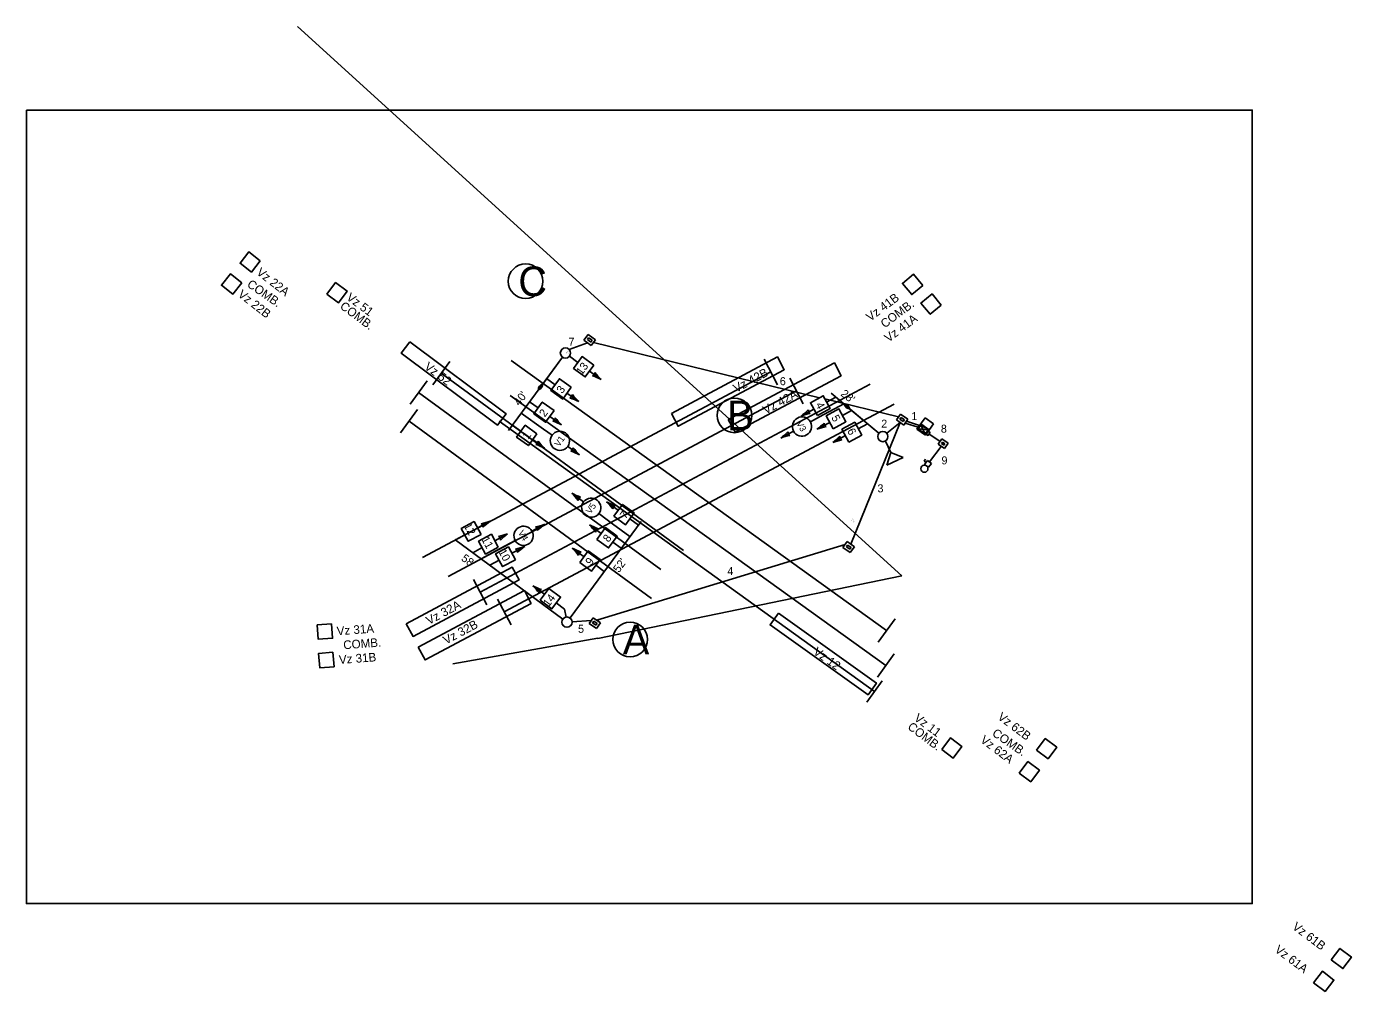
# Model space of a CAD drawing. Extents: x 973817 to 2958182, y 703625 to 1593455.
# Drawn here: x 977687 to 978239, y 704200 to 704601 of the extents above; entities that cross this region are included whole.
import ezdxf

# ---------------------------------------------------------------- set-up
doc = ezdxf.new("R2010")
doc.units = 0
for name, color, linetype in [('R_Fin Surface', 7, 'Continuous'), ('S_PAVEMENT_CROWN', 7, 'Continuous'), ('T_Conduit', 7, 'Continuous'), ('T_Detection Annot', 7, 'Continuous'), ('T_Detection Zones', 7, 'Continuous'), ('T_Drafting', 7, 'Continuous'), ('T_Indications', 7, 'Continuous'), ('T_Mast Arm', 7, 'Continuous'), ('T_PHASE SYMBOLS', 7, 'Continuous')]:
    doc.layers.add(name, color=color, linetype=linetype)

msp = doc.modelspace()

# ---------------------------------------------------------------- linework, layer by layer
at = {"layer": 'R_Fin Surface'}
for p, q in [((977856.23, 704452.09), (977863.31, 704461.77)), ((978045.08, 704349.89), (977888.82, 704462.22)), ((977994.09, 704462.73), (977999.73, 704452.14)), ((977846.83, 704444.09), (977853.92, 704453.78)), ((977996.91, 704457.43), (977852.01, 704380.26)), ((977859.77, 704456.93), (977960.59, 704383.21)), ((978004.77, 704454.82), (978010.41, 704444.23)), ((977850.37, 704448.94), (977951.19, 704375.21)), ((978007.59, 704449.52), (977862.69, 704372.35)), ((977875.95, 704365.88), (978038.26, 704452.33)), ((977885.98, 704357.63), (978048.28, 704444.08)), ((978044.74, 704335.35), (977888.49, 704447.68)), ((977842.85, 704432.14), (977849.93, 704441.83)), ((977846.39, 704436.98), (977947.21, 704363.26)), ((978040.05, 704324.55), (977883.8, 704436.89)), ((977878.8, 704360.53), (977873.16, 704371.13)), ((977888.83, 704352.28), (977883.19, 704362.87)), ((978041.57, 704345.01), (978048.58, 704354.76)), ((978041.24, 704330.47), (978048.25, 704340.22)), ((978036.84, 704320.09), (978043.27, 704329.02))]:
    msp.add_line(p, q, dxfattribs=at)
at = {"layer": 'S_PAVEMENT_CROWN'}
for p, q in [((978051.43, 704372.62), (977799.98, 704601.11)), ((978051.43, 704372.62), (977924.96, 704346.55)), ((977924.86, 704346.64), (977864.6, 704336.01))]:
    msp.add_line(p, q, dxfattribs=at)
msp.add_lwpolyline([(977687.19, 704566.32), (978197.19, 704566.32), (978197.19, 704236.32), (977687.19, 704236.32)], close=True, dxfattribs=at)
at = {"layer": 'T_Conduit'}
for p, q in [((977920.68, 704469.56), (977913, 704466.77)), ((978017.19, 704446.73), (977923.06, 704469.65)), ((978050.02, 704438.74), (978019.43, 704446.19)), ((978030.16, 704385.75), (978050.69, 704436.46)), ((978045.16, 704431.9), (978050.69, 704436.46)), ((978052.8, 704436.18), (978058.23, 704434.41)), ((978053.34, 704436.92), (978058.77, 704435.15)), ((978062.72, 704431.63), (978067.32, 704428.53)), ((978062.91, 704419.99), (978067.81, 704426.49)), ((978027.79, 704385.67), (977924.5, 704354.13)), ((977914.22, 704353.53), (977922.13, 704354.04))]:
    msp.add_line(p, q, dxfattribs=at)
at = {"layer": 'T_Detection Zones'}
for points in [[(977784.48, 704503.7), (977780.79, 704498.97), (977776.06, 704502.67), (977779.75, 704507.4)], [(977776.74, 704494.52), (977773.05, 704489.79), (977768.32, 704493.48), (977772.01, 704498.21)], [(978060.13, 704493.45), (978056.3, 704498.07), (978051.68, 704494.24), (978055.51, 704489.62)], [(977812.23, 704489.8), (977815.81, 704494.62), (977820.62, 704491.04), (977817.04, 704486.22)], [(978067.84, 704485.27), (978064.01, 704489.89), (978059.39, 704486.06), (978063.22, 704481.44)], [(977846.73, 704470.02), (977886.75, 704440.04), (977883.15, 704435.24), (977843.13, 704465.22)], [(977955.53, 704440.14), (977999.66, 704463.65), (978002.48, 704458.35), (977958.35, 704434.85)], [(977979.22, 704437.67), (978023.35, 704461.18), (978026.17, 704455.88), (977982.04, 704432.38)], [(977845.21, 704352.72), (977889.34, 704376.23), (977892.16, 704370.93), (977848.03, 704347.43)], [(977850.22, 704342.97), (977894.35, 704366.48), (977897.17, 704361.18), (977853.04, 704337.68)], [(978000.09, 704357.06), (978040.82, 704328.05), (978037.34, 704323.17), (977996.61, 704352.18)], [(977814.13, 704352.65), (977814.57, 704346.67), (977808.59, 704346.22), (977808.14, 704352.2)], [(977814.71, 704340.82), (977815.16, 704334.84), (977809.18, 704334.39), (977808.73, 704340.37)], [(978068.03, 704300.41), (978071.64, 704305.21), (978076.44, 704301.6), (978072.83, 704296.8)], [(978107.48, 704300.16), (978111.09, 704304.96), (978115.88, 704301.35), (978112.28, 704296.55)], [(978100.27, 704290.57), (978103.88, 704295.36), (978108.67, 704291.76), (978105.07, 704286.96)], [(978230.12, 704212.88), (978233.73, 704217.68), (978238.52, 704214.08), (978234.92, 704209.28)], [(978222.77, 704203.4), (978226.43, 704208.15), (978231.19, 704204.49), (978227.53, 704199.74)]]:
    msp.add_lwpolyline(points, close=True, dxfattribs=at)
at = {"layer": 'T_Drafting'}
for p, q in [((977919.16, 704470.65), (977920.86, 704473.02)), ((977919.16, 704470.65), (977922.2, 704468.46)), ((977920.56, 704470.88), (977921.09, 704471.63)), ((977920.56, 704470.88), (977921.98, 704469.86)), ((977920.86, 704473.02), (977923.91, 704470.83)), ((977921.09, 704471.63), (977922.51, 704470.6)), ((977921.98, 704469.86), (977922.51, 704470.6)), ((977922.2, 704468.46), (977923.91, 704470.83)), ((977910.18, 704463.59), (977887.74, 704433.09)), ((977910.18, 704463.59), (977901.84, 704452.25)), ((978040.35, 704433.2), (978022.08, 704448.56)), ((978041.88, 704431.92), (978029.57, 704442.26)), ((978049.17, 704437.55), (978050.88, 704439.92)), ((978049.17, 704437.55), (978052.22, 704435.36)), ((978050.57, 704437.78), (978051.1, 704438.53)), ((978050.57, 704437.78), (978051.99, 704436.76)), ((978050.88, 704439.92), (978053.92, 704437.73)), ((978051.1, 704438.53), (978052.52, 704437.5)), ((978051.99, 704436.76), (978052.52, 704437.5)), ((978052.22, 704435.36), (978053.92, 704437.73)), ((978061.06, 704438.33), (978057.71, 704433.67)), ((978064.57, 704435.8), (978061.06, 704438.33)), ((978061.22, 704431.14), (978057.71, 704433.67)), ((978059.38, 704435.44), (978058.17, 704433.75)), ((978061.14, 704431.6), (978058.17, 704433.75)), ((978058.17, 704433.75), (978062.36, 704433.29)), ((978062.82, 704433.37), (978059.31, 704435.9)), ((978062.36, 704433.29), (978059.38, 704435.44)), ((978061.13, 704431.62), (978059.38, 704435.44)), ((978062.36, 704433.29), (978061.14, 704431.6)), ((978064.57, 704435.8), (978061.22, 704431.14)), ((978044.57, 704428.69), (978046.89, 704423.87)), ((978066.52, 704427.42), (978068.11, 704429.63)), ((978066.52, 704427.42), (978069.11, 704425.56)), ((978067.91, 704427.65), (978068.34, 704428.24)), ((978067.91, 704427.65), (978068.88, 704426.95)), ((978068.11, 704429.63), (978070.7, 704427.77)), ((978068.34, 704428.24), (978069.3, 704427.55)), ((978068.88, 704426.95), (978069.3, 704427.55)), ((978069.11, 704425.56), (978070.7, 704427.77)), ((978045.24, 704418.64), (978046.89, 704423.87)), ((978052, 704421.89), (978045.24, 704418.64)), ((978046.89, 704423.87), (978052, 704421.89)), ((978061.31, 704421.19), (978060.71, 704420.39)), ((978062.11, 704420.59), (978060.9, 704418.99)), ((978063.7, 704419.38), (978062.11, 704420.59)), ((978061.5, 704419.79), (978060.71, 704420.39)), ((978062.5, 704417.79), (978060.9, 704418.99)), ((978063.7, 704419.38), (978062.5, 704417.79)), ((978026.93, 704384.48), (978028.64, 704386.85)), ((978026.93, 704384.48), (978029.98, 704382.29)), ((978028.33, 704384.71), (978028.87, 704385.45)), ((978028.33, 704384.71), (978029.75, 704383.69)), ((978028.64, 704386.85), (978031.68, 704384.66)), ((978028.87, 704385.45), (978030.29, 704384.43)), ((978029.75, 704383.69), (978030.29, 704384.43)), ((978029.98, 704382.29), (978031.68, 704384.66)), ((977921.27, 704352.85), (977922.98, 704355.22)), ((977922.98, 704355.22), (977926.02, 704353.03)), ((977921.27, 704352.85), (977924.32, 704350.66)), ((977922.67, 704353.08), (977923.2, 704353.83)), ((977922.67, 704353.08), (977924.09, 704352.06)), ((977923.2, 704353.83), (977924.62, 704352.8)), ((977924.09, 704352.06), (977924.62, 704352.8)), ((977924.32, 704350.66), (977926.02, 704353.03))]:
    msp.add_line(p, q, dxfattribs=at)
msp.add_lwpolyline([(978061.54, 704431.59), (978062.3, 704431.05), (978063.14, 704432.22), (978062.38, 704432.76)], dxfattribs=at)
for centre, radius in [((977911.45, 704465.31), 2.13), ((978043.51, 704430.55), 2.13), ((978060.8, 704417.19), 1.5), ((977912.09, 704353.4), 2.13)]:
    msp.add_circle(centre, radius, dxfattribs=at)
for centre, major_axis in [((977901.09, 704451.22), (-0.75, -1.02)), ((978028.6, 704443.07), (-0.971, 0.815))]:
    msp.add_ellipse(centre, major_axis=major_axis, ratio=0.40798, dxfattribs=at)
at = {"layer": 'T_Indications'}
for p, q in [((977916.59, 704461.37), (977913.08, 704463.94)), ((977907.15, 704452.14), (977903.62, 704454.67)), ((977921.48, 704457.8), (977926.36, 704454.23)), ((977912.07, 704448.6), (977916.98, 704445.08)), ((977900.04, 704442.47), (977896.51, 704445.01)), ((978017.17, 704438.72), (978027.25, 704444.2)), ((978020.14, 704444.89), (978023.96, 704446.96)), ((977902.36, 704433.61), (977893.02, 704440.27)), ((977904.96, 704438.94), (977909.86, 704435.41)), ((978014.82, 704441.99), (978009.51, 704439.1)), ((978017.17, 704438.72), (978013.37, 704436.65)), ((978026.72, 704439.36), (978030.53, 704441.43)), ((977892.92, 704432.8), (977889.39, 704435.34)), ((977902.36, 704433.61), (977905.88, 704431.1)), ((978006.34, 704432.82), (978001.01, 704429.93)), ((978021.39, 704436.46), (978016.09, 704433.57)), ((978033.29, 704433.83), (978037.11, 704435.9)), ((977897.84, 704429.27), (977902.74, 704425.74)), ((977912.39, 704426.45), (977917.33, 704422.93)), ((978027.97, 704430.93), (978022.67, 704428.04)), ((977918.97, 704403.35), (977914.12, 704406.98)), ((977928.84, 704395.96), (977925.38, 704398.56)), ((977933.4, 704399.9), (977928.52, 704403.47)), ((977874.87, 704392.54), (977880.18, 704395.42)), ((977897.53, 704391.18), (977902.85, 704394.07)), ((977926.29, 704390.24), (977921.41, 704393.8)), ((977938.29, 704396.33), (977941.8, 704393.76)), ((977869.55, 704389.64), (977865.71, 704387.55)), ((977882.06, 704387.24), (977887.37, 704390.13)), ((977886.7, 704385.29), (977890.5, 704387.35)), ((977876.74, 704384.35), (977872.9, 704382.26)), ((977889.18, 704382.01), (977894.48, 704384.89)), ((977919.17, 704380.57), (977914.3, 704384.14)), ((977931.18, 704386.66), (977934.69, 704384.1)), ((977883.85, 704379.11), (977880.01, 704377.02)), ((977924.07, 704377), (977927.57, 704374.43)), ((977902.72, 704364.94), (977897.85, 704368.51)), ((977907.62, 704361.37), (977911.12, 704358.8)), ((977911.09, 704358.82), (977911.7, 704355.49))]:
    msp.add_line(p, q, dxfattribs=at)
for points in [[(977923.27, 704460.24), (977919.69, 704455.35), (977914.8, 704458.93), (977918.38, 704463.82)], [(977913.84, 704451.06), (977910.3, 704446.14), (977905.38, 704449.68), (977908.92, 704454.6)], [(977906.73, 704441.39), (977903.19, 704436.48), (977898.27, 704440.01), (977901.81, 704444.93)], [(978016.26, 704439.33), (978013.37, 704444.65), (978018.69, 704447.55), (978021.58, 704442.22)], [(978022.84, 704433.8), (978019.95, 704439.12), (978025.27, 704442.02), (978028.16, 704436.69)], [(977899.61, 704431.72), (977896.07, 704426.81), (977891.15, 704430.34), (977894.69, 704435.26)], [(978029.42, 704428.27), (978026.52, 704433.59), (978031.85, 704436.49), (978034.74, 704431.16)], [(977931.6, 704397.46), (977935.19, 704402.35), (977940.08, 704398.77), (977936.5, 704393.88)], [(977876.32, 704389.88), (977873.42, 704395.2), (977868.1, 704392.3), (977871, 704386.98)], [(977883.51, 704384.58), (977880.61, 704389.9), (977875.29, 704387.01), (977878.19, 704381.69)], [(977924.5, 704387.79), (977928.08, 704392.68), (977932.97, 704389.1), (977929.39, 704384.22)], [(977890.63, 704379.35), (977887.73, 704384.67), (977882.4, 704381.77), (977885.3, 704376.45)], [(977917.38, 704378.13), (977920.96, 704383.02), (977925.86, 704379.44), (977922.28, 704374.55)], [(977900.93, 704362.5), (977904.51, 704367.39), (977909.41, 704363.81), (977905.83, 704358.92)]]:
    msp.add_lwpolyline(points, close=True, dxfattribs=at)
for points in [[(977928.84, 704395.96), (977931.04, 704394.32), (977938.24, 704388.93)], [(977886.7, 704385.29), (977884.29, 704383.98), (977876.38, 704379.68)]]:
    msp.add_lwpolyline(points, dxfattribs=at)
for centre, major_axis, ratio, start_param, end_param in [((977922.11, 704457.34), (1.63, -0.07), 0.998816, 5.137096, 6.248777), ((977912.71, 704428.14), (-29.45, 1.22), 0.998816, 4.272384, 4.407439), ((977947.12, 704475.12), (29.45, -1.22), 0.998816, 3.836841, 3.971897), ((977912.7, 704448.15), (1.63, -0.05), 0.998816, 5.137096, 6.248777), ((977937.57, 704466.13), (29.46, -0.99), 0.998816, 3.836841, 3.971897), ((977903.54, 704418.88), (-29.46, 0.99), 0.998816, 4.272384, 4.407439), ((977905.59, 704438.48), (1.63, -0.05), 0.998816, 5.137096, 6.248777), ((977896.42, 704409.21), (-29.46, 0.99), 0.998816, 4.272384, 4.407439), ((977930.46, 704456.46), (29.46, -0.99), 0.998816, 3.836841, 3.971897), ((977991.75, 704462.58), (13.68, 26.1), 0.998816, 4.272384, 4.407439), ((978019.53, 704411.4), (-13.68, -26.1), 0.998816, 3.836841, 3.971897), ((978014.14, 704441.62), (-0.76, -1.44), 0.998816, 5.137096, 6.248777), ((977983.22, 704453.4), (25.89, 14.08), 0.999186, 4.862665, 4.997721), ((978005.64, 704432.44), (-1.43, -0.78), 0.999186, 5.727378, 6.839059), ((977998.33, 704457.05), (13.68, 26.1), 0.998816, 4.272384, 4.407439), ((978026.11, 704405.88), (-13.68, -26.1), 0.998816, 3.836841, 3.971897), ((978020.71, 704436.09), (-0.76, -1.44), 0.998816, 5.137096, 6.248777), ((977898.47, 704428.81), (1.63, -0.05), 0.998816, 5.137096, 6.248777), ((977889.31, 704399.54), (-29.46, 0.99), 0.998816, 4.272384, 4.407439), ((977923.34, 704446.79), (29.46, -0.99), 0.998816, 3.836841, 3.971897), ((978011.05, 704402.24), (-25.89, -14.08), 0.999186, 4.427123, 4.562178), ((978004.9, 704451.52), (13.68, 26.1), 0.998816, 4.272384, 4.407439), ((978032.68, 704400.35), (-13.68, -26.1), 0.998816, 3.836841, 3.971897), ((978027.29, 704430.56), (-0.76, -1.44), 0.998816, 5.137096, 6.248777), ((977913.04, 704425.99), (1.33, -0.95), 0.999186, 5.727378, 6.839059), ((977904.01, 704396.66), (-23.99, 17.12), 0.999186, 4.862665, 4.997721), ((977937.83, 704444.07), (23.99, -17.12), 0.999186, 4.427123, 4.562178), ((977893.13, 704386.3), (25.74, 14.35), 0.999533, 0.134406, 0.269462), ((977928.05, 704432.95), (-25.74, -14.35), 0.999533, 0.569949, 0.705004), ((977918.34, 704403.83), (-1.42, -0.79), 0.999533, 4.576253, 5.687935), ((977907.75, 704382.58), (-29.45, 1.09), 0.998761, 3.832296, 3.967352), ((977942.17, 704429.56), (29.45, -1.09), 0.998761, 4.267839, 4.402894), ((977932.77, 704400.36), (-1.63, 0.06), 0.998761, 5.132551, 6.244232), ((977870.11, 704423.09), (29.34, -2.83), 0.998761, 5.021884, 5.156939), ((977875.55, 704392.9), (1.62, -0.16), 0.998761, 0.038953, 1.150634), ((977897.99, 704371.96), (-29.34, 2.83), 0.998761, 5.457426, 5.592482), ((977892.8, 704421.77), (23.41, -17.9), 0.999533, 5.578181, 5.713237), ((977898.23, 704391.56), (-1.29, 0.99), 0.999533, 3.736843, 4.848524), ((977920.66, 704370.59), (-23.41, 17.9), 0.999533, 6.013724, 6.148779), ((977900.64, 704372.92), (-29.45, 1.09), 0.998761, 3.832296, 3.967352), ((977935.06, 704419.89), (29.45, -1.09), 0.998761, 4.267839, 4.402894), ((977877.3, 704417.8), (29.34, -2.83), 0.998761, 5.021884, 5.156939), ((977882.74, 704387.61), (1.62, -0.16), 0.998761, 0.038953, 1.150634), ((977905.18, 704366.67), (-29.34, 2.83), 0.998761, 5.457426, 5.592482), ((977925.66, 704390.69), (-1.63, 0.06), 0.998761, 5.132551, 6.244232), ((977884.42, 704412.56), (29.34, -2.83), 0.998761, 5.021884, 5.156939), ((977889.86, 704382.37), (1.62, -0.16), 0.998761, 0.038953, 1.150634), ((977912.29, 704361.43), (-29.34, 2.83), 0.998761, 5.457426, 5.592482), ((977893.53, 704363.25), (-29.45, 1.09), 0.998761, 3.832296, 3.967352), ((977927.95, 704410.22), (29.45, -1.09), 0.998761, 4.267839, 4.402894), ((977918.55, 704381.03), (-1.63, 0.06), 0.998761, 5.132551, 6.244232), ((977877.08, 704347.62), (-29.45, 1.09), 0.998761, 3.832296, 3.967352), ((977911.5, 704394.59), (29.45, -1.09), 0.998761, 4.267839, 4.402894), ((977902.1, 704365.4), (-1.63, 0.06), 0.998761, 5.132551, 6.244232)]:
    msp.add_ellipse(centre, major_axis=major_axis, ratio=ratio, start_param=start_param, end_param=end_param, dxfattribs=at)
for centre, major_axis, ratio in [((978009.85, 704434.74), (-3.51, -1.91), 0.999186), ((977909.14, 704428.78), (3.26, -2.32), 0.999186), ((977922.18, 704400.95), (3.49, 1.95), 0.999533), ((977894.02, 704389.26), (-3.18, 2.43), 0.999533)]:
    msp.add_ellipse(centre, major_axis=major_axis, ratio=ratio, dxfattribs=at)
at = {"layer": 'T_Mast Arm'}
for p, q in [((977913.35, 704355.11), (977942.92, 704395.27)), ((977910.37, 704354.66), (977865.38, 704387.78))]:
    msp.add_line(p, q, dxfattribs=at)
at = {"layer": 'T_PHASE SYMBOLS'}
for centre in [(977894.87, 704495.14), (977981.74, 704439.38), (977938.35, 704346.15)]:
    msp.add_circle(centre, 7.21, dxfattribs=at)

# ---------------------------------------------------------------- texts
for s, rotation, p in [('N=704465.31  ', 53.247, (977911.56, 704465.22)), ('E=977911.45  ', 53.247, (977911.75, 704465.08)), ('Sta=18+31.96 ', 53.247, (977911.94, 704464.94)), ("Off=38.74' ", 53.247, (977912.14, 704464.79)), ('11.81m ', 53.247, (977912.33, 704464.65)), ('N=704395.48  ', 53.9355, (978030.48, 704395.4)), ('E=978030.37  ', 53.9355, (978030.68, 704395.26)), ('Sta=16+94.25 ', 53.9355, (978030.87, 704395.12)), ("Off=53.13' ", 53.9355, (978031.07, 704394.97)), ('16.19m ', 53.9355, (978031.26, 704394.83)), ('N=704354.13  ', 53.6305, (977924.61, 704354.04)), ('E=977924.50  ', 53.6305, (977924.8, 704353.9)), ('Sta=17+55.26 ', 53.6305, (977925, 704353.76)), ("Off=42.79' ", 53.6305, (977925.19, 704353.62)), ('13.04m ', 53.6305, (977925.38, 704353.47))]:
    msp.add_text(s, height=0.14, rotation=rotation).set_placement(p)
at = {"layer": 'S_PAVEMENT_CROWN'}
for s, p in [('7', (977912.72, 704468.36)), ('6', (978000.65, 704451.91)), ('2', (978042.84, 704434.26)), ('1', (978055.38, 704437.38)), ('8', (978067.67, 704432.16)), ('9', (978067.92, 704418.98)), ('3', (978041.29, 704407.35)), ('4', (977978.8, 704372.96)), ('5', (977916.7, 704348.93))]:
    msp.add_text(s, height=3.33, dxfattribs=at).set_placement(p)
at = {"layer": 'T_Detection Annot'}
for s, rotation, p in [('Vz 22A', 322.0317, (977782.59, 704498.27)), ('COMB.', 325.1942, (977778.67, 704493.17)), ('Vz 22B', 322.0317, (977774.85, 704489.09)), ('Vz 51', 323.3602, (977819.99, 704487.76)), ('Vz 41B', 36.8133, (978038.24, 704478.31)), ('COMB.', 36.8133, (978044.28, 704475.5)), ('COMB.', 323.3602, (977817.3, 704484.14)), ('Vz 41A', 36.8133, (978045.86, 704469.59)), ('Vz 52', 323.1629, (977852.43, 704458.95)), ('Vz 42B', 28.146, (977982.48, 704448.73)), ('Vz 42A', 28.146, (977994.76, 704439.72)), ('Vz 32A', 28.146, (977854.64, 704352.16)), ('Vz 32B', 28.146, (977861.73, 704343.98)), ('Vz 31A', 4.2558, (977816.42, 704347.86)), ('COMB.', 4.2558, (977819.14, 704342.06)), ('Vz 31B', 4.2558, (977817.34, 704335.95)), ('Vz 12', 324.5368, (978014.24, 704340.31)), ('Vz 11', 323.0735, (978056.22, 704312.81)), ('Vz 62B', 323.0735, (978090.97, 704313.27)), ('COMB.', 323.0735, (978053.51, 704309.21)), ('Vz 62A', 323.0735, (978083.76, 704303.68)), ('COMB.', 325.1942, (978088.68, 704306.42)), ('Vz 61B', 323.0735, (978213.6, 704226)), ('Vz 61A', 323.0735, (978206.28, 704216.49))]:
    msp.add_text(s, height=3.6, rotation=rotation, dxfattribs=at).set_placement(p)
at = {"layer": 'T_Drafting'}
for s, p in [('12', (977869, 704393.48)), ('11', (977876.36, 704387.88)), ('10', (977883.46, 704382.67))]:
    msp.add_text(s, height=3.33, rotation=298.6026, dxfattribs=at).set_placement(p)
at = {"layer": 'T_Indications'}
for s, height, rotation, p in [('13', 3.33, 53.6308, (977918.26, 704455.85)), ("40'", 3.33, 53.7695, (977892.33, 704443.1)), ('3', 3.33, 54.0916, (977910.12, 704448.19)), ("28'", 3.33, 321.6566, (978025.7, 704447.84)), ('4', 3.33, 298.3521, (978015.44, 704443.81)), ('2', 3.33, 54.0916, (977902.9, 704438.44)), ('V3', 2.66, 299.6283, (978007.4, 704436.11)), ('5', 3.33, 298.3521, (978021.96, 704438.48)), ('1', 3.33, 54.0916, (977895.94, 704429.12)), ('6', 3.33, 298.3521, (978028.54, 704432.95)), ('V1', 2.66, 55.5776, (977908.85, 704426.1)), ('V5', 2.66, 55.5776, (977921.91, 704398.17)), ('7', 3.33, 53.7695, (977936.46, 704396.01)), ('V4', 2.66, 300.9667, (977891.62, 704390.6)), ('8', 3.33, 53.7695, (977929.4, 704386.34)), ("58'", 3.33, 323.7695, (977867.8, 704379.28)), ('9', 3.33, 53.7695, (977922.12, 704376.68)), ("52'", 3.33, 53.7695, (977933.68, 704373.69)), ('14', 3.33, 53.7695, (977904.51, 704359.47))]:
    msp.add_text(s, height=height, rotation=rotation, dxfattribs=at).set_placement(p)
at = {"layer": 'T_PHASE SYMBOLS'}
for s, p in [('C', (977891.85, 704488.97)), ('B', (977978.72, 704433.21))]:
    msp.add_text(s, height=12.34, rotation=360, dxfattribs=at).set_placement(p)
msp.add_text('A', height=12.34, dxfattribs=at).set_placement((977935.32, 704339.98))

doc.saveas('drawing.dxf')
